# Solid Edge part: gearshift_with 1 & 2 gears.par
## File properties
Author: vinurabandara
Template: iso metric part.par
Last saved by: Nimesh.N
Revision: 34
Application: Solid Edge
Density: 7833.000 kg/m^3
Accuracy: 0.990
Username: Nimesh.N
Material: Steel
Face Style: Steel
Fill Style: ANSI32(Steel)
Virtual Style: Machined steel
Grouping: Metals\Steel
LibraryName: Materials
Coef. of Thermal Exp: 1.3e-05
Thermal Conductivity: 32.0
Specific Heat: 481.0
Modulus of Elasticity: 199947953000.0
Poisson's Ratio: 0.29
Yield Stress: 262000766.0
Ultimate Stress: 358527364.0
Elongation: 0.0
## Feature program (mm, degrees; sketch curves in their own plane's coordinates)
sketch for "unnamed Protrusion 1" plane through (0, 0, 0) normal (0, -1, 0) x-axis (1, 0, 0)
  line (-34.0588, 82.2253) -> (-45.3609, 109.511)
  line (-45.3609, 109.511) -> (45.3609, 109.511)
  line (34.0588, 82.2253) -> (45.3609, 109.511)
extrude "unnamed Protrusion 1" add finite 5 along +normal
sketch for "ExtrudedProtrusion_2" plane through (0, -5, 95.8681) normal (0, -1, 0) x-axis (1, 0, 0)
  line (-45.3609, 13.6428) -> (45.3609, 13.6428)
  line (45.3609, 13.6428) -> (45.3609, 19.6428)
  line (45.3609, 19.6428) -> (-45.3609, 19.6428)
  line (-45.3609, 19.6428) -> (-45.3609, 13.6428)
  dimension (linear) = 45.3609
extrude "ExtrudedProtrusion_2" add finite 10 along -normal
mirror "unnamed Mirror 1" of "ExtrudedProtrusion_2", "unnamed Protrusion 1"
pattern "unnamed Pattern 1"
sketch for "ExtrudedProtrusion_4" plane through (0, 5, 115.511) normal (0, 0, 1) x-axis (1, 0, 0)
extrude "ExtrudedProtrusion_4" add finite 250 along +normal
fillet "Round_1" radius 2.5
sketch for "ExtrudedCutout_2" plane through (0, 0, 292) normal (0, 0, 1) x-axis (1, 0, 0)
extrude "ExtrudedCutout_2" cut finite 186 along +normal  Profile_Plane1_Distance = 292 mm
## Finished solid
Body 1: solid body, 24 faces, 54 edges, 32 vertices.
  Faces by surface: plane 18, cylinder 6
  Edges by curve: line 46, circle 4, ellipse 4
Bounding box of the edges (mm): 90.722 x 20.000 x 209.775, from (-45.3609, -5, 82.2253) to (45.3609, 15, 292).
Cylindrical faces by radius (mm): R2.5 x4, R89 x2
Planar faces by outward normal: +x 2, +y 3, +z 3, -x 2, -y 3, -z 1, oblique 4
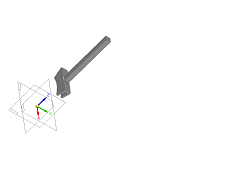
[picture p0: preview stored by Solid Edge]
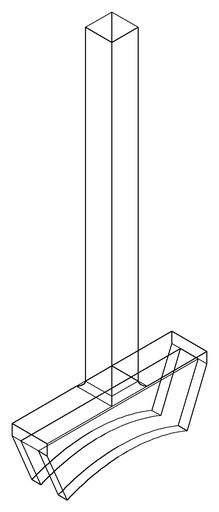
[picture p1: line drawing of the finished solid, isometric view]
